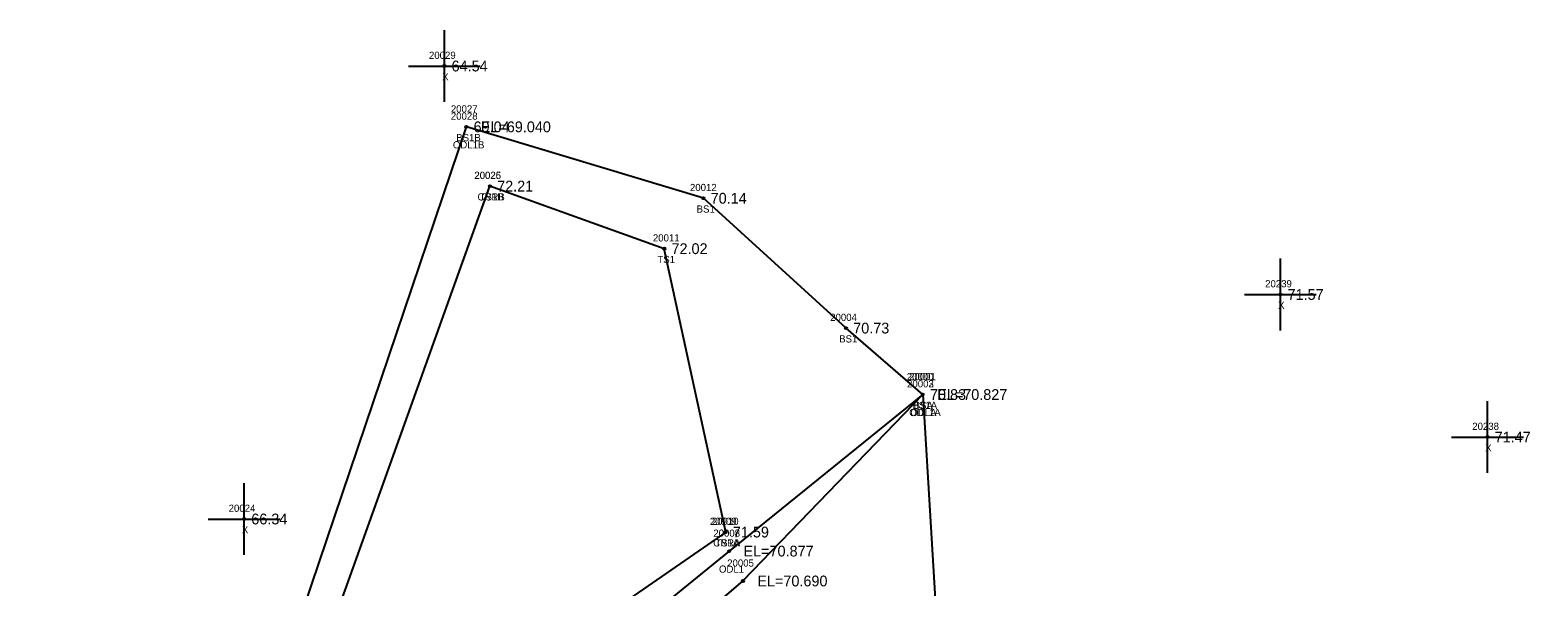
# Model space of a CAD drawing. Extents: x 2505300 to 2506184, y 912965 to 913825.
# Drawn here: x 2505661.1 to 2505870.9, y 913662.4 to 913739.9 of the extents above; entities that cross this region are included whole.
import ezdxf

# ---------------------------------------------------------------- set-up
doc = ezdxf.new("R2010")
doc.units = 0
for name, color, linetype in [('RD_DTM_BkLn2', 7, 'Continuous'), ('RD_DTM_BkLn_txCode', 7, 'Continuous'), ('RD_EX_H2O', 7, 'Continuous'), ('RD_EX_H2O_txCode', 7, 'Continuous'), ('RD_EX_Misc', 7, 'Continuous'), ('RD_EX_Misc_txCode', 7, 'Continuous'), ('RD_EX_TX_H2O_ELEV', 7, 'Continuous'), ('RD_EX_TX_Misc_ELEV', 7, 'Continuous'), ('RD_SMD_Locator', 7, 'Continuous')]:
    doc.layers.add(name, color=color, linetype=linetype)

msp = doc.modelspace()

# ---------------------------------------------------------------- linework, layer by layer
at = {"layer": 'RD_DTM_BkLn2'}
for points in [[(2505785.34, 913689.17), (2505774.65, 913698.42), (2505754.81, 913716.5), (2505721.81, 913726.44)], [(2505757.9, 913670.02), (2505749.36, 913709.48), (2505725.09, 913718.19)], [(2505785.34, 913689.17), (2505788.84, 913631.4), (2505793.89, 913566.95)]]:
    msp.add_lwpolyline(points, dxfattribs=at)
at = {"layer": 'RD_EX_H2O'}
for points in [[(2505785.34, 913689.17), (2505758.38, 913667.37), (2505737.34, 913650.24), (2505720.51, 913632.48), (2505699.15, 913659.34), (2505721.81, 913726.44)], [(2505757.9, 913670.02), (2505731.18, 913651.53), (2505719.28, 913634.92), (2505703.6, 913658.16), (2505725.09, 913718.19)], [(2505785.34, 913689.17), (2505760.31, 913663.21), (2505743.1, 913648.56), (2505723.59, 913620.14), (2505672.59, 913632.18), (2505661.09, 913622.14), (2505712.19, 913587.82), (2505787.26, 913549.76), (2505800.1, 913534.14), (2505825.87, 913510.39), (2505850.5, 913511.75), (2505883.26, 913521.88), (2505912.04, 913531.86), (2505948.81, 913534.96), (2505974.98, 913528.19), (2506003.87, 913517.71), (2506051.32, 913503.49), (2506114.3, 913484.75), (2506121.45, 913493.97), (2506156, 913550.08)]]:
    msp.add_lwpolyline(points, dxfattribs=at)
at = {"layer": 'RD_EX_Misc'}
for p, q in [((2505718.75, 913729.91), (2505718.75, 913739.91)), ((2505713.75, 913734.91), (2505723.75, 913734.91)), ((2505835.11, 913698.1), (2505835.11, 913708.1)), ((2505830.11, 913703.1), (2505840.11, 913703.1)), ((2505863.94, 913678.25), (2505863.94, 913688.25)), ((2505858.94, 913683.25), (2505868.94, 913683.25)), ((2505690.87, 913666.84), (2505690.87, 913676.84)), ((2505685.87, 913671.84), (2505695.87, 913671.84))]:
    msp.add_line(p, q, dxfattribs=at)
at = {"layer": 'RD_SMD_Locator'}
for centre in [(2505718.75, 913734.91), (2505721.81, 913726.44), (2505721.81, 913726.44), (2505725.09, 913718.19), (2505725.09, 913718.19), (2505754.81, 913716.5), (2505749.36, 913709.48), (2505835.11, 913703.1), (2505774.65, 913698.42), (2505785.34, 913689.17), (2505785.34, 913689.17), (2505785.34, 913689.17), (2505785.34, 913689.17), (2505863.94, 913683.25), (2505690.87, 913671.84), (2505757.9, 913670.02), (2505757.9, 913670.02), (2505758.38, 913667.37), (2505760.31, 913663.21)]:
    msp.add_circle(centre, 0.15, dxfattribs=at)

# ---------------------------------------------------------------- texts
at = {"layer": 'RD_DTM_BkLn_txCode'}
for s, p in [('20028', (2505719.65, 913727.44)), ('BS1B', (2505720.39, 913724.44)), ('20026', (2505722.91, 913719.19)), ('20012', (2505752.93, 913717.5)), ('TS1B', (2505723.66, 913716.19)), ('BS1', (2505753.86, 913714.5)), ('20011', (2505747.77, 913710.48)), ('TS1', (2505748.4, 913707.48)), ('20004', (2505772.45, 913699.42)), ('BS1', (2505773.7, 913696.42)), ('20002', (2505783.15, 913690.17)), ('20003', (2505783.15, 913690.17)), ('BS1A', (2505783.91, 913687.17)), ('BSA', (2505784.08, 913687.17)), ('20010', (2505755.98, 913671.02)), ('TS1A', (2505756.45, 913668.02))]:
    msp.add_text(s, height=1, dxfattribs=at).set_placement(p)
at = {"layer": 'RD_EX_H2O_txCode'}
for s, p in [('20027', (2505719.65, 913728.44)), ('ODL1B', (2505719.93, 913723.44)), ('20025', (2505722.93, 913719.19)), ('CRRB', (2505723.36, 913716.19)), ('20000', (2505783.11, 913691.17)), ('20001', (2505783.43, 913691.17)), ('ODL1A', (2505783.45, 913686.17)), ('ODLA', (2505783.61, 913686.17)), ('20009', (2505755.7, 913671.02)), ('20008', (2505756.18, 913669.37)), ('CRRA', (2505756.16, 913668.02)), ('20005', (2505758.11, 913665.21)), ('ODL1', (2505756.97, 913664.37))]:
    msp.add_text(s, height=1, dxfattribs=at).set_placement(p)
at = {"layer": 'RD_EX_Misc_txCode'}
for s, p in [('20029', (2505716.6, 913735.91)), ('X', (2505718.44, 913732.91)), ('20239', (2505832.99, 913704.1)), ('X', (2505834.79, 913701.1)), ('20238', (2505861.82, 913684.25)), ('X', (2505863.62, 913681.25)), ('20024', (2505688.72, 913672.84)), ('X', (2505690.56, 913669.84))]:
    msp.add_text(s, height=1, dxfattribs=at).set_placement(p)
at = {"layer": 'RD_EX_TX_H2O_ELEV'}
for s, p in [('EL=69.040', (2505723.81, 913725.69)), ('72.21', (2505726.09, 913717.44)), ('EL=70.827', (2505787.34, 913688.42)), ('EL=70.827', (2505787.34, 913688.42)), ('71.59', (2505758.9, 913669.27)), ('EL=70.877', (2505760.38, 913666.62)), ('EL=70.690', (2505762.31, 913662.46))]:
    msp.add_text(s, height=1.5, dxfattribs=at).set_placement(p)
at = {"layer": 'RD_EX_TX_Misc_ELEV'}
for s, p in [('64.54', (2505719.75, 913734.16)), ('69.04', (2505722.81, 913725.69)), ('72.21', (2505726.09, 913717.44)), ('70.14', (2505755.81, 913715.75)), ('72.02', (2505750.36, 913708.73)), ('71.57', (2505836.11, 913702.35)), ('70.73', (2505775.65, 913697.67)), ('70.83', (2505786.34, 913688.42)), ('70.83', (2505786.34, 913688.42)), ('71.47', (2505864.94, 913682.5)), ('66.34', (2505691.87, 913671.09)), ('71.59', (2505758.9, 913669.27))]:
    msp.add_text(s, height=1.5, dxfattribs=at).set_placement(p)

doc.saveas('drawing.dxf')
